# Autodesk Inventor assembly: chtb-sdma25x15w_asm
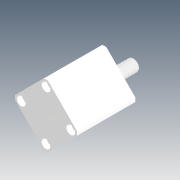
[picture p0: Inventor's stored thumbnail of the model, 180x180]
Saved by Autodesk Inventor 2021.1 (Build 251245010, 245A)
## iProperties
Company: Microsoft
Created: 2018-05
Part Number: chtb-sdma25x15w_asm
Description: STEP AP214
Document SubType Name: Assembly
Designer: user
Title: chtb-sdma25x15w_asm.STEP
Author: Windows
Revision Number: ÈÎºÎ
Sending System: SolidWorks 2015
Preprocessor: SwSTEP 2.0
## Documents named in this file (4)
- D:\Vault_2016\Projekty\Clamptek\Hydraulic\CHTB\CHTB-25\Inventor\chtb-sdma25x15w\chtb-sdma25x15w_asm.iam
- D:\Vault_2016\Projekty\Clamptek\Hydraulic\CHTB\CHTB-25\Inventor\chtb-sdma25x15w\CHTB-25QG.ipt
- D:\Vault_2016\Projekty\Clamptek\Hydraulic\CHTB\CHTB-25\Inventor\chtb-sdma25x15w\CHTB-SDMA25X15NBT.ipt
- D:\Vault_2016\Projekty\Clamptek\Hydraulic\CHTB\CHTB-25\Inventor\chtb-sdma25x15w\CHTB-SDMA25X15WHSG.ipt
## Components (3 placed, 3 different names)
1. CHTB-25QG_1
2. CHTB-SDMA25X15NBT_2
3. CHTB-SDMA25X15WHSG_3
